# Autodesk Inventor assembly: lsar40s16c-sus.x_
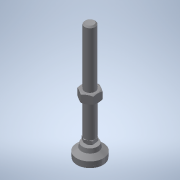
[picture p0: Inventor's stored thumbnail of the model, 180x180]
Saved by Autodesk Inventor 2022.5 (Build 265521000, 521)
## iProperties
Part Number: lsar40s16c-sus.x_
Material: 一般
Document SubType Name: Assembly
Designer: ImaoCorp
Sending System: SOLIDWORKS 2017-2017317
MC: AMD64
MC_MODEL: Intel64 Family 6 Model 60 Stepping 3, GenuineIntel
OS: Windows_NT
FRU: Parasolid Version 29.0, build 201,  4-17-2017
FORMAT: text
GUISE: transmit
KEY: lsar40s16c-sus
FILE: lsar40s16c-sus.x_t
DATE: Mon Jul 01 18:01:42 2019
Author: ImaoCorp
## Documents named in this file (3)
- X:\14_SW2022-Inv2022\00_全2023-1023新製品(TCC)まで\l\lsar40s16c-sus\LSAR40S16C-SUS.iam
- X:\14_SW2022-Inv2022\00_全2023-1023新製品(TCC)まで\l\lsar40s16c-sus\lsar40s16c-sus_01.ipt
- X:\14_SW2022-Inv2022\00_全2023-1023新製品(TCC)まで\l\lsar40s16c-sus\lsar40s16c-sus_02.ipt
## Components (2 placed, 2 different names)
1. lsar40s16c-sus_01
2. lsar40s16c-sus_02
